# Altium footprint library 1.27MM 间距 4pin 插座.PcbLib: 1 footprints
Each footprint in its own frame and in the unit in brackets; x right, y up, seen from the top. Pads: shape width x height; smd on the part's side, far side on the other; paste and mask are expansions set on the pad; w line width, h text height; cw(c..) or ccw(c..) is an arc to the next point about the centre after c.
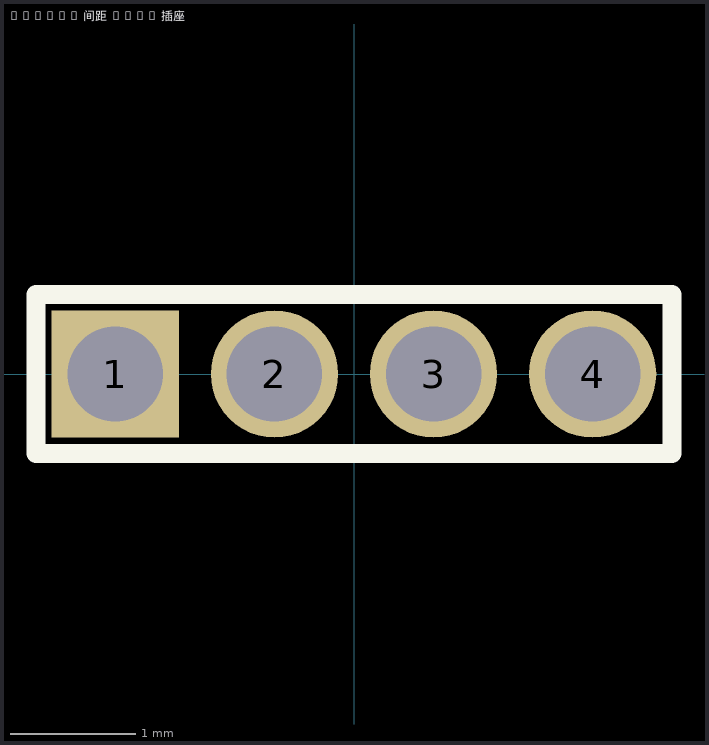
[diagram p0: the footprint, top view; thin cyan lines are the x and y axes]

## 1.27MM 间距 4pin 插座 [mil] "1.27MM 间距 4pin 插座"
pads (4):
  rect 40x40 hole 30: 1(-75,0)
  round 40 hole 30: 2(-25,0) 3(25,0) 4(75,0)
Top Overlay:
  lines w6: -100,-25 100,-25 100,25 -100,25 -100,-25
